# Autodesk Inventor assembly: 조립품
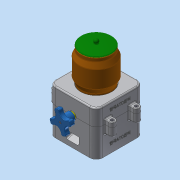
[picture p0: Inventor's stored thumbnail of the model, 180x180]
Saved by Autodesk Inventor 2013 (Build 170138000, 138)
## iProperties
Created: 2018-01
Part Number: 조립품
Document SubType Name: Assembly
Designer: dgall
Author: dgall
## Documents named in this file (9)
- C:\Users\dgall\Desktop\480107V1026\조립품.iam
- C:\Users\dgall\Desktop\480107V1026\본체.ipt
- C:\Users\dgall\Desktop\480107V1026\본체커버.ipt
- C:\Users\dgall\Desktop\480107V1026\볼트 M3x12.ipt
- C:\Users\dgall\Desktop\480107V1026\볼트 M4x12.ipt
- C:\Users\dgall\Desktop\480107V1026\용기.ipt
- C:\Users\dgall\Desktop\480107V1026\용기캡.ipt
- C:\Users\dgall\Desktop\480107V1026\핸들.ipt
- C:\Users\dgall\Desktop\480107V1026\핸들축.ipt
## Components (2 placed, 2 different names)
1. 핸들:1
2. 핸들축:1 — 각도:2
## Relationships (1: Angle 1)
- 각도:2 [Angle]: 핸들축:1
